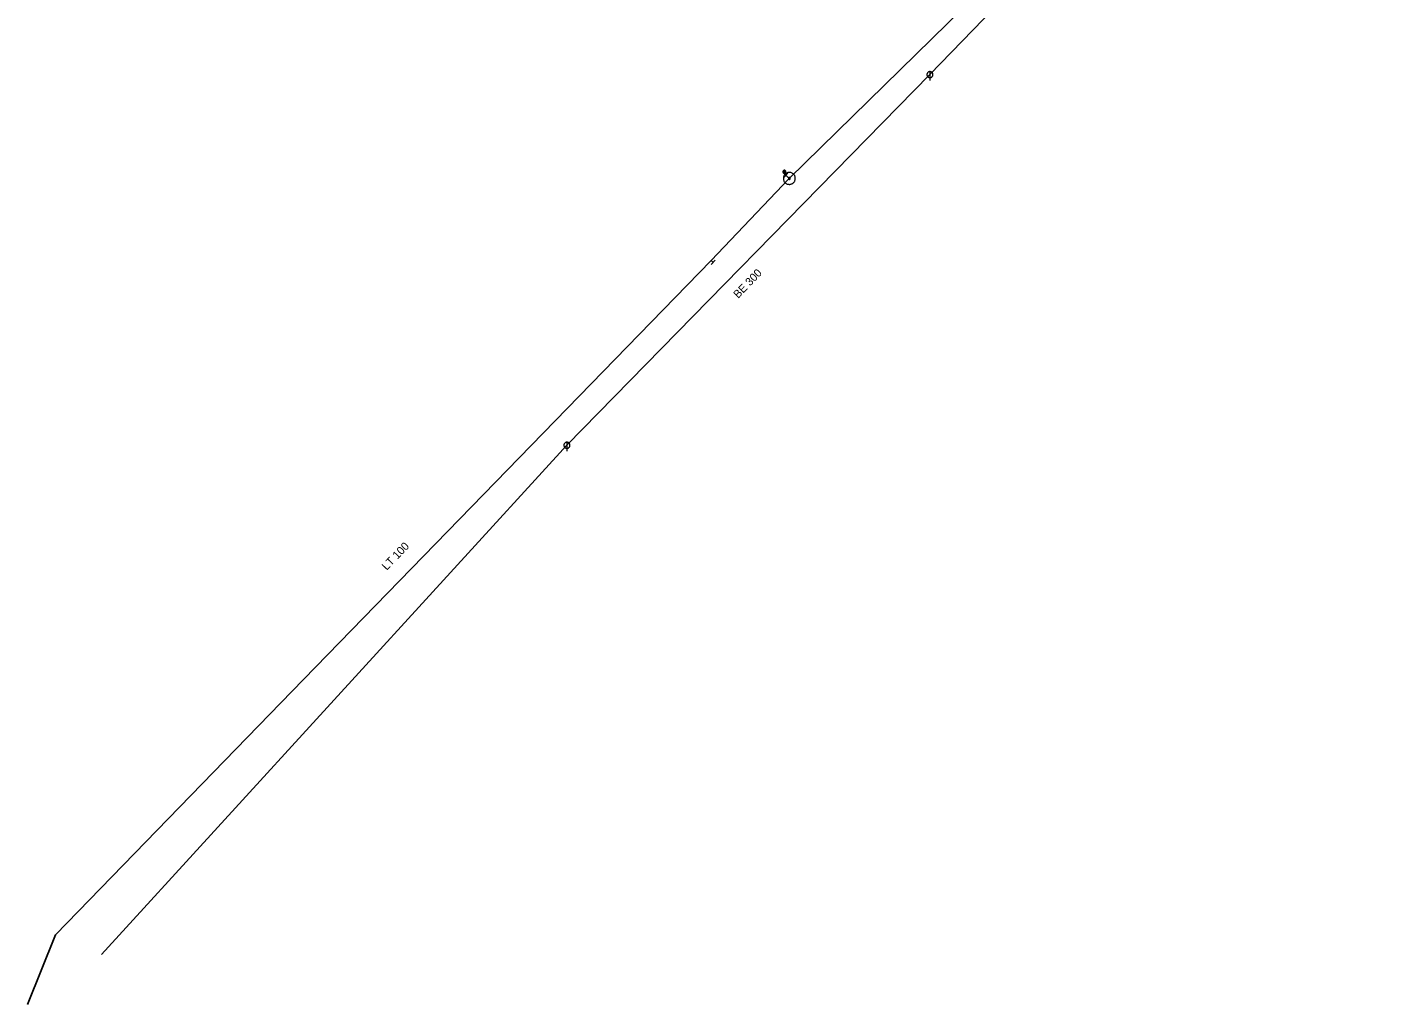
# Model space of a CAD drawing. Extents: x -687515 to -686506, y -974029 to -973461.
# Drawn here: x -687452.1 to -687338.1, y -974010.5 to -973929.1 of the extents above; entities that cross this region are included whole.
import ezdxf
from ezdxf.enums import TextEntityAlignment as Align

# ---------------------------------------------------------------- set-up
doc = ezdxf.new("R2010")
doc.units = 0
doc.header["$LTSCALE"] = 0.27
for name, color, linetype, lineweight in [('1', 7, 'Continuous', 13), ('14', 7, 'Continuous', 25), ('17', 7, 'Continuous', 25), ('22', 7, 'Continuous', 13), ('34', 7, 'Continuous', 13), ('47', 7, 'Continuous', 13), ('9', 7, 'Continuous', 13)]:
    doc.layers.add(name, color=color, linetype=linetype, lineweight=lineweight)

msp = doc.modelspace()

# ---------------------------------------------------------------- linework, layer by layer
at = {"layer": '14'}
for p, q in [((-687359.932, -973915.43), (-687376.923, -973933.074)), ((-687376.923, -973933.074), (-687407.16, -973963.95)), ((-687407.16, -973963.95), (-687445.923, -974006.379))]:
    msp.add_line(p, q, dxfattribs=at)
at = {"layer": '14', "lineweight": 13}
for p, q in [((-687388.929, -973941.459), (-687389.049, -973941.169)), ((-687388.929, -973941.459), (-687388.637, -973941.719)), ((-687395.154, -973948.56), (-687394.977, -973948.712))]:
    msp.add_line(p, q, dxfattribs=at)
at = {"layer": '17'}
for points in [[(-687388.637, -973941.719), (-687347.688, -973901.59), (-687341.168, -973894.641), (-687338.055, -973891.483)], [(-687452.1, -974010.546), (-687449.768, -974004.74), (-687429.115, -973983.449), (-687395.154, -973948.56), (-687388.637, -973941.719)]]:
    msp.add_lwpolyline(points, dxfattribs=at)
at = {"layer": '22'}
for p, q in [((-687376.922, -973932.822), (-687376.923, -973933.566)), ((-687407.159, -973963.698), (-687407.16, -973964.441))]:
    msp.add_line(p, q, dxfattribs=at)
for points in [[(-687376.671, -973933.074), (-687376.672, -973933.048), (-687376.676, -973933.022), (-687376.682, -973932.996), (-687376.692, -973932.972), (-687376.704, -973932.948), (-687376.718, -973932.926), (-687376.735, -973932.905), (-687376.753, -973932.887), (-687376.774, -973932.87), (-687376.796, -973932.856), (-687376.82, -973932.844), (-687376.844, -973932.834), (-687376.87, -973932.828), (-687376.896, -973932.824), (-687376.922, -973932.822), (-687376.948, -973932.823), (-687376.974, -973932.827), (-687377, -973932.833), (-687377.025, -973932.843), (-687377.048, -973932.855), (-687377.07, -973932.869), (-687377.091, -973932.886), (-687377.109, -973932.904), (-687377.126, -973932.925), (-687377.14, -973932.947), (-687377.152, -973932.971), (-687377.162, -973932.995), (-687377.169, -973933.021), (-687377.173, -973933.047), (-687377.174, -973933.073), (-687377.174, -973933.099), (-687377.17, -973933.125), (-687377.163, -973933.151), (-687377.153, -973933.176), (-687377.141, -973933.199), (-687377.127, -973933.221), (-687377.11, -973933.242), (-687377.092, -973933.26), (-687377.071, -973933.277), (-687377.049, -973933.291), (-687377.026, -973933.303), (-687377.001, -973933.313), (-687376.975, -973933.32), (-687376.949, -973933.324), (-687376.923, -973933.326), (-687376.897, -973933.325), (-687376.871, -973933.321), (-687376.845, -973933.314), (-687376.821, -973933.304), (-687376.797, -973933.292), (-687376.775, -973933.278), (-687376.754, -973933.261), (-687376.736, -973933.243), (-687376.719, -973933.222), (-687376.705, -973933.2), (-687376.693, -973933.177), (-687376.683, -973933.152), (-687376.677, -973933.126), (-687376.673, -973933.1)], [(-687406.908, -973963.95), (-687406.909, -973963.924), (-687406.913, -973963.898), (-687406.919, -973963.872), (-687406.929, -973963.848), (-687406.941, -973963.824), (-687406.955, -973963.802), (-687406.972, -973963.781), (-687406.99, -973963.763), (-687407.011, -973963.746), (-687407.033, -973963.732), (-687407.057, -973963.72), (-687407.081, -973963.71), (-687407.107, -973963.704), (-687407.133, -973963.7), (-687407.159, -973963.698), (-687407.185, -973963.699), (-687407.211, -973963.703), (-687407.237, -973963.709), (-687407.262, -973963.719), (-687407.285, -973963.731), (-687407.307, -973963.745), (-687407.328, -973963.762), (-687407.346, -973963.78), (-687407.363, -973963.801), (-687407.377, -973963.823), (-687407.389, -973963.847), (-687407.399, -973963.871), (-687407.406, -973963.897), (-687407.41, -973963.923), (-687407.412, -973963.949), (-687407.411, -973963.975), (-687407.407, -973964.001), (-687407.4, -973964.027), (-687407.39, -973964.052), (-687407.378, -973964.075), (-687407.364, -973964.097), (-687407.347, -973964.118), (-687407.329, -973964.136), (-687407.308, -973964.153), (-687407.286, -973964.167), (-687407.263, -973964.179), (-687407.238, -973964.189), (-687407.212, -973964.196), (-687407.186, -973964.2), (-687407.16, -973964.201), (-687407.134, -973964.201), (-687407.108, -973964.197), (-687407.082, -973964.19), (-687407.058, -973964.18), (-687407.034, -973964.168), (-687407.012, -973964.154), (-687406.991, -973964.137), (-687406.973, -973964.119), (-687406.956, -973964.098), (-687406.942, -973964.076), (-687406.93, -973964.053), (-687406.92, -973964.028), (-687406.914, -973964.002), (-687406.91, -973963.976)]]:
    msp.add_lwpolyline(points, close=True, dxfattribs=at)
at = {"layer": '34'}
for p, q in [((-687389.103, -973941.635), (-687388.754, -973941.282)), ((-687395.138, -973948.899), (-687394.815, -973948.524))]:
    msp.add_line(p, q, dxfattribs=at)
at = {"layer": '47'}
for points in [[(-687388.284, -973941.363), (-687388.323, -973941.329), (-687388.366, -973941.298), (-687388.411, -973941.273), (-687388.459, -973941.251), (-687388.509, -973941.235), (-687388.561, -973941.225), (-687388.612, -973941.22), (-687388.665, -973941.22), (-687388.716, -973941.225), (-687388.768, -973941.236), (-687388.818, -973941.253), (-687388.865, -973941.275), (-687388.911, -973941.3), (-687388.953, -973941.332), (-687388.992, -973941.366), (-687389.026, -973941.405), (-687389.057, -973941.448), (-687389.083, -973941.494), (-687389.104, -973941.541), (-687389.12, -973941.591), (-687389.13, -973941.643), (-687389.136, -973941.695), (-687389.136, -973941.747), (-687389.13, -973941.799), (-687389.119, -973941.85), (-687389.102, -973941.9), (-687389.081, -973941.948), (-687389.055, -973941.993), (-687389.023, -973942.035), (-687388.989, -973942.074), (-687388.95, -973942.108), (-687388.907, -973942.139), (-687388.862, -973942.166), (-687388.814, -973942.186), (-687388.764, -973942.202), (-687388.713, -973942.213), (-687388.661, -973942.219), (-687388.608, -973942.218), (-687388.556, -973942.212), (-687388.505, -973942.201), (-687388.455, -973942.184), (-687388.408, -973942.164), (-687388.362, -973942.137), (-687388.32, -973942.105), (-687388.281, -973942.071), (-687388.247, -973942.032), (-687388.216, -973941.989), (-687388.19, -973941.944), (-687388.169, -973941.896), (-687388.153, -973941.846), (-687388.142, -973941.795), (-687388.137, -973941.743), (-687388.137, -973941.691), (-687388.143, -973941.639), (-687388.154, -973941.587), (-687388.171, -973941.537), (-687388.192, -973941.49), (-687388.218, -973941.444), (-687388.25, -973941.402)], [(-687388.579, -973941.66), (-687388.585, -973941.654), (-687388.592, -973941.65), (-687388.599, -973941.646), (-687388.607, -973941.642), (-687388.616, -973941.639), (-687388.624, -973941.638), (-687388.633, -973941.636), (-687388.641, -973941.636), (-687388.65, -973941.638), (-687388.658, -973941.639), (-687388.667, -973941.642), (-687388.674, -973941.646), (-687388.681, -973941.65), (-687388.688, -973941.654), (-687388.695, -973941.661), (-687388.701, -973941.667), (-687388.705, -973941.674), (-687388.709, -973941.681), (-687388.713, -973941.689), (-687388.716, -973941.698), (-687388.717, -973941.706), (-687388.719, -973941.715), (-687388.719, -973941.723), (-687388.718, -973941.732), (-687388.716, -973941.74), (-687388.713, -973941.749), (-687388.709, -973941.756), (-687388.705, -973941.763), (-687388.701, -973941.77), (-687388.694, -973941.777), (-687388.688, -973941.783), (-687388.681, -973941.787), (-687388.674, -973941.791), (-687388.666, -973941.795), (-687388.657, -973941.798), (-687388.65, -973941.8), (-687388.64, -973941.801), (-687388.632, -973941.801), (-687388.623, -973941.8), (-687388.615, -973941.798), (-687388.606, -973941.795), (-687388.599, -973941.791), (-687388.592, -973941.787), (-687388.585, -973941.783), (-687388.578, -973941.776), (-687388.572, -973941.77), (-687388.568, -973941.763), (-687388.564, -973941.756), (-687388.56, -973941.748), (-687388.557, -973941.739), (-687388.555, -973941.732), (-687388.554, -973941.722), (-687388.554, -973941.714), (-687388.556, -973941.705), (-687388.557, -973941.697), (-687388.56, -973941.688), (-687388.564, -973941.681), (-687388.568, -973941.674), (-687388.572, -973941.667)]]:
    msp.add_lwpolyline(points, close=True, dxfattribs=at)
at = {"layer": '9'}
for points in [[(-687388.923, -973941.169), (-687388.924, -973941.156), (-687388.926, -973941.143), (-687388.929, -973941.13), (-687388.934, -973941.118), (-687388.94, -973941.106), (-687388.947, -973941.095), (-687388.955, -973941.085), (-687388.965, -973941.075), (-687388.975, -973941.067), (-687388.986, -973941.059), (-687388.998, -973941.054), (-687389.01, -973941.049), (-687389.023, -973941.046), (-687389.036, -973941.044), (-687389.049, -973941.043), (-687389.062, -973941.044), (-687389.075, -973941.046), (-687389.088, -973941.049), (-687389.1, -973941.054), (-687389.112, -973941.059), (-687389.123, -973941.067), (-687389.133, -973941.075), (-687389.143, -973941.085), (-687389.151, -973941.095), (-687389.158, -973941.106), (-687389.164, -973941.118), (-687389.169, -973941.13), (-687389.172, -973941.143), (-687389.174, -973941.156), (-687389.175, -973941.169), (-687389.174, -973941.182), (-687389.172, -973941.195), (-687389.169, -973941.208), (-687389.164, -973941.22), (-687389.158, -973941.232), (-687389.151, -973941.243), (-687389.143, -973941.253), (-687389.133, -973941.263), (-687389.123, -973941.271), (-687389.112, -973941.278), (-687389.1, -973941.284), (-687389.088, -973941.289), (-687389.075, -973941.292), (-687389.062, -973941.294), (-687389.049, -973941.295), (-687389.036, -973941.294), (-687389.023, -973941.292), (-687389.01, -973941.289), (-687388.998, -973941.284), (-687388.986, -973941.278), (-687388.975, -973941.271), (-687388.965, -973941.263), (-687388.955, -973941.253), (-687388.947, -973941.243), (-687388.94, -973941.232), (-687388.934, -973941.22), (-687388.929, -973941.208), (-687388.926, -973941.195), (-687388.924, -973941.182)], [(-687388.943, -973941.169), (-687388.943, -973941.157), (-687388.945, -973941.147), (-687388.948, -973941.136), (-687388.952, -973941.126), (-687388.957, -973941.116), (-687388.963, -973941.107), (-687388.97, -973941.098), (-687388.978, -973941.09), (-687388.987, -973941.083), (-687388.996, -973941.077), (-687389.006, -973941.072), (-687389.016, -973941.068), (-687389.027, -973941.065), (-687389.038, -973941.063), (-687389.049, -973941.063), (-687389.06, -973941.063), (-687389.071, -973941.065), (-687389.082, -973941.068), (-687389.092, -973941.072), (-687389.102, -973941.077), (-687389.111, -973941.083), (-687389.12, -973941.09), (-687389.128, -973941.098), (-687389.135, -973941.107), (-687389.141, -973941.116), (-687389.146, -973941.126), (-687389.15, -973941.136), (-687389.153, -973941.147), (-687389.155, -973941.157), (-687389.155, -973941.169), (-687389.155, -973941.18), (-687389.153, -973941.191), (-687389.15, -973941.202), (-687389.146, -973941.212), (-687389.141, -973941.222), (-687389.135, -973941.231), (-687389.128, -973941.24), (-687389.12, -973941.248), (-687389.111, -973941.255), (-687389.102, -973941.261), (-687389.092, -973941.266), (-687389.082, -973941.27), (-687389.071, -973941.273), (-687389.06, -973941.275), (-687389.049, -973941.275), (-687389.038, -973941.275), (-687389.027, -973941.273), (-687389.016, -973941.27), (-687389.006, -973941.266), (-687388.996, -973941.261), (-687388.987, -973941.255), (-687388.978, -973941.248), (-687388.97, -973941.24), (-687388.963, -973941.231), (-687388.957, -973941.222), (-687388.952, -973941.212), (-687388.948, -973941.202), (-687388.945, -973941.191), (-687388.943, -973941.18)], [(-687388.962, -973941.169), (-687388.963, -973941.16), (-687388.964, -973941.151), (-687388.967, -973941.142), (-687388.97, -973941.134), (-687388.974, -973941.126), (-687388.979, -973941.118), (-687388.985, -973941.111), (-687388.991, -973941.105), (-687388.998, -973941.099), (-687389.006, -973941.094), (-687389.014, -973941.09), (-687389.022, -973941.087), (-687389.031, -973941.084), (-687389.04, -973941.083), (-687389.049, -973941.081), (-687389.058, -973941.083), (-687389.067, -973941.084), (-687389.076, -973941.087), (-687389.084, -973941.09), (-687389.092, -973941.094), (-687389.1, -973941.099), (-687389.107, -973941.105), (-687389.113, -973941.111), (-687389.119, -973941.118), (-687389.124, -973941.126), (-687389.128, -973941.134), (-687389.131, -973941.142), (-687389.134, -973941.151), (-687389.135, -973941.16), (-687389.136, -973941.169), (-687389.135, -973941.178), (-687389.134, -973941.187), (-687389.131, -973941.196), (-687389.128, -973941.204), (-687389.124, -973941.212), (-687389.119, -973941.22), (-687389.113, -973941.227), (-687389.107, -973941.233), (-687389.1, -973941.239), (-687389.092, -973941.244), (-687389.084, -973941.248), (-687389.076, -973941.251), (-687389.067, -973941.254), (-687389.058, -973941.255), (-687389.049, -973941.256), (-687389.04, -973941.255), (-687389.031, -973941.254), (-687389.022, -973941.251), (-687389.014, -973941.248), (-687389.006, -973941.244), (-687388.998, -973941.239), (-687388.991, -973941.233), (-687388.985, -973941.227), (-687388.979, -973941.22), (-687388.974, -973941.212), (-687388.97, -973941.204), (-687388.967, -973941.196), (-687388.964, -973941.187), (-687388.963, -973941.178)], [(-687388.982, -973941.169), (-687388.982, -973941.162), (-687388.984, -973941.155), (-687388.985, -973941.148), (-687388.988, -973941.142), (-687388.991, -973941.136), (-687388.995, -973941.13), (-687388.999, -973941.124), (-687389.004, -973941.119), (-687389.01, -973941.115), (-687389.016, -973941.111), (-687389.022, -973941.108), (-687389.028, -973941.105), (-687389.035, -973941.104), (-687389.042, -973941.102), (-687389.049, -973941.102), (-687389.056, -973941.102), (-687389.063, -973941.104), (-687389.07, -973941.105), (-687389.076, -973941.108), (-687389.083, -973941.111), (-687389.088, -973941.115), (-687389.094, -973941.119), (-687389.099, -973941.124), (-687389.103, -973941.13), (-687389.107, -973941.136), (-687389.11, -973941.142), (-687389.113, -973941.148), (-687389.115, -973941.155), (-687389.116, -973941.162), (-687389.116, -973941.169), (-687389.116, -973941.176), (-687389.115, -973941.183), (-687389.113, -973941.19), (-687389.11, -973941.196), (-687389.107, -973941.203), (-687389.103, -973941.208), (-687389.099, -973941.214), (-687389.094, -973941.219), (-687389.088, -973941.223), (-687389.083, -973941.227), (-687389.076, -973941.23), (-687389.07, -973941.233), (-687389.063, -973941.235), (-687389.056, -973941.236), (-687389.049, -973941.236), (-687389.042, -973941.236), (-687389.035, -973941.235), (-687389.028, -973941.233), (-687389.022, -973941.23), (-687389.016, -973941.227), (-687389.01, -973941.223), (-687389.004, -973941.219), (-687388.999, -973941.214), (-687388.995, -973941.208), (-687388.991, -973941.203), (-687388.988, -973941.196), (-687388.985, -973941.19), (-687388.984, -973941.183), (-687388.982, -973941.176)], [(-687389.002, -973941.169), (-687389.002, -973941.164), (-687389.003, -973941.159), (-687389.004, -973941.154), (-687389.006, -973941.15), (-687389.008, -973941.145), (-687389.011, -973941.141), (-687389.014, -973941.138), (-687389.018, -973941.134), (-687389.021, -973941.131), (-687389.025, -973941.128), (-687389.03, -973941.126), (-687389.034, -973941.124), (-687389.039, -973941.123), (-687389.044, -973941.122), (-687389.049, -973941.122), (-687389.054, -973941.122), (-687389.059, -973941.123), (-687389.064, -973941.124), (-687389.068, -973941.126), (-687389.073, -973941.128), (-687389.077, -973941.131), (-687389.081, -973941.134), (-687389.084, -973941.138), (-687389.087, -973941.141), (-687389.09, -973941.145), (-687389.092, -973941.15), (-687389.094, -973941.154), (-687389.095, -973941.159), (-687389.096, -973941.164), (-687389.096, -973941.169), (-687389.096, -973941.174), (-687389.095, -973941.179), (-687389.094, -973941.184), (-687389.092, -973941.188), (-687389.09, -973941.193), (-687389.087, -973941.197), (-687389.084, -973941.201), (-687389.081, -973941.204), (-687389.077, -973941.206), (-687389.073, -973941.21), (-687389.068, -973941.212), (-687389.064, -973941.214), (-687389.059, -973941.215), (-687389.054, -973941.216), (-687389.049, -973941.216), (-687389.044, -973941.216), (-687389.039, -973941.215), (-687389.034, -973941.214), (-687389.03, -973941.212), (-687389.025, -973941.21), (-687389.021, -973941.206), (-687389.018, -973941.204), (-687389.014, -973941.201), (-687389.011, -973941.197), (-687389.008, -973941.193), (-687389.006, -973941.188), (-687389.004, -973941.184), (-687389.003, -973941.179), (-687389.002, -973941.174)], [(-687389.022, -973941.169), (-687389.022, -973941.166), (-687389.022, -973941.163), (-687389.023, -973941.161), (-687389.024, -973941.157), (-687389.025, -973941.155), (-687389.027, -973941.153), (-687389.029, -973941.151), (-687389.031, -973941.149), (-687389.033, -973941.147), (-687389.035, -973941.145), (-687389.038, -973941.144), (-687389.041, -973941.143), (-687389.043, -973941.142), (-687389.046, -973941.142), (-687389.049, -973941.142), (-687389.052, -973941.142), (-687389.055, -973941.142), (-687389.058, -973941.143), (-687389.06, -973941.144), (-687389.063, -973941.145), (-687389.065, -973941.147), (-687389.068, -973941.149), (-687389.07, -973941.151), (-687389.071, -973941.153), (-687389.073, -973941.155), (-687389.074, -973941.157), (-687389.075, -973941.161), (-687389.076, -973941.163), (-687389.076, -973941.166), (-687389.077, -973941.169), (-687389.076, -973941.172), (-687389.076, -973941.175), (-687389.075, -973941.178), (-687389.074, -973941.18), (-687389.073, -973941.183), (-687389.071, -973941.184), (-687389.07, -973941.188), (-687389.068, -973941.19), (-687389.065, -973941.191), (-687389.063, -973941.193), (-687389.06, -973941.194), (-687389.058, -973941.195), (-687389.055, -973941.196), (-687389.052, -973941.196), (-687389.049, -973941.197), (-687389.046, -973941.196), (-687389.043, -973941.196), (-687389.041, -973941.195), (-687389.038, -973941.194), (-687389.035, -973941.193), (-687389.033, -973941.191), (-687389.031, -973941.19), (-687389.029, -973941.188), (-687389.027, -973941.184), (-687389.025, -973941.183), (-687389.024, -973941.18), (-687389.023, -973941.178), (-687389.022, -973941.175), (-687389.022, -973941.172)], [(-687389.041, -973941.169), (-687389.041, -973941.168), (-687389.041, -973941.167), (-687389.042, -973941.167), (-687389.042, -973941.166), (-687389.042, -973941.165), (-687389.043, -973941.164), (-687389.043, -973941.164), (-687389.044, -973941.163), (-687389.044, -973941.163), (-687389.045, -973941.162), (-687389.046, -973941.162), (-687389.047, -973941.162), (-687389.047, -973941.161), (-687389.048, -973941.161), (-687389.049, -973941.161), (-687389.05, -973941.161), (-687389.051, -973941.161), (-687389.051, -973941.162), (-687389.052, -973941.162), (-687389.053, -973941.162), (-687389.054, -973941.163), (-687389.054, -973941.163), (-687389.055, -973941.164), (-687389.055, -973941.164), (-687389.056, -973941.165), (-687389.056, -973941.166), (-687389.057, -973941.167), (-687389.057, -973941.167), (-687389.057, -973941.168), (-687389.057, -973941.169), (-687389.057, -973941.17), (-687389.057, -973941.171), (-687389.057, -973941.171), (-687389.056, -973941.172), (-687389.056, -973941.173), (-687389.055, -973941.174), (-687389.055, -973941.174), (-687389.054, -973941.175), (-687389.054, -973941.175), (-687389.053, -973941.176), (-687389.052, -973941.176), (-687389.051, -973941.177), (-687389.051, -973941.177), (-687389.05, -973941.177), (-687389.049, -973941.177), (-687389.048, -973941.177), (-687389.047, -973941.177), (-687389.047, -973941.177), (-687389.046, -973941.176), (-687389.045, -973941.176), (-687389.044, -973941.175), (-687389.044, -973941.175), (-687389.043, -973941.174), (-687389.043, -973941.174), (-687389.042, -973941.173), (-687389.042, -973941.172), (-687389.042, -973941.171), (-687389.041, -973941.171), (-687389.041, -973941.17)]]:
    msp.add_lwpolyline(points, close=True, dxfattribs=at)

# ---------------------------------------------------------------- texts
at = {"layer": '1'}
for s, p in [('BE 300', (-687391.881, -973950.704)), ('LT 100', (-687421.211, -973973.414))]:
    msp.add_text(s, height=0.6667, rotation=46, dxfattribs=at).set_placement(p, align=Align.CENTER)

doc.saveas('drawing.dxf')
